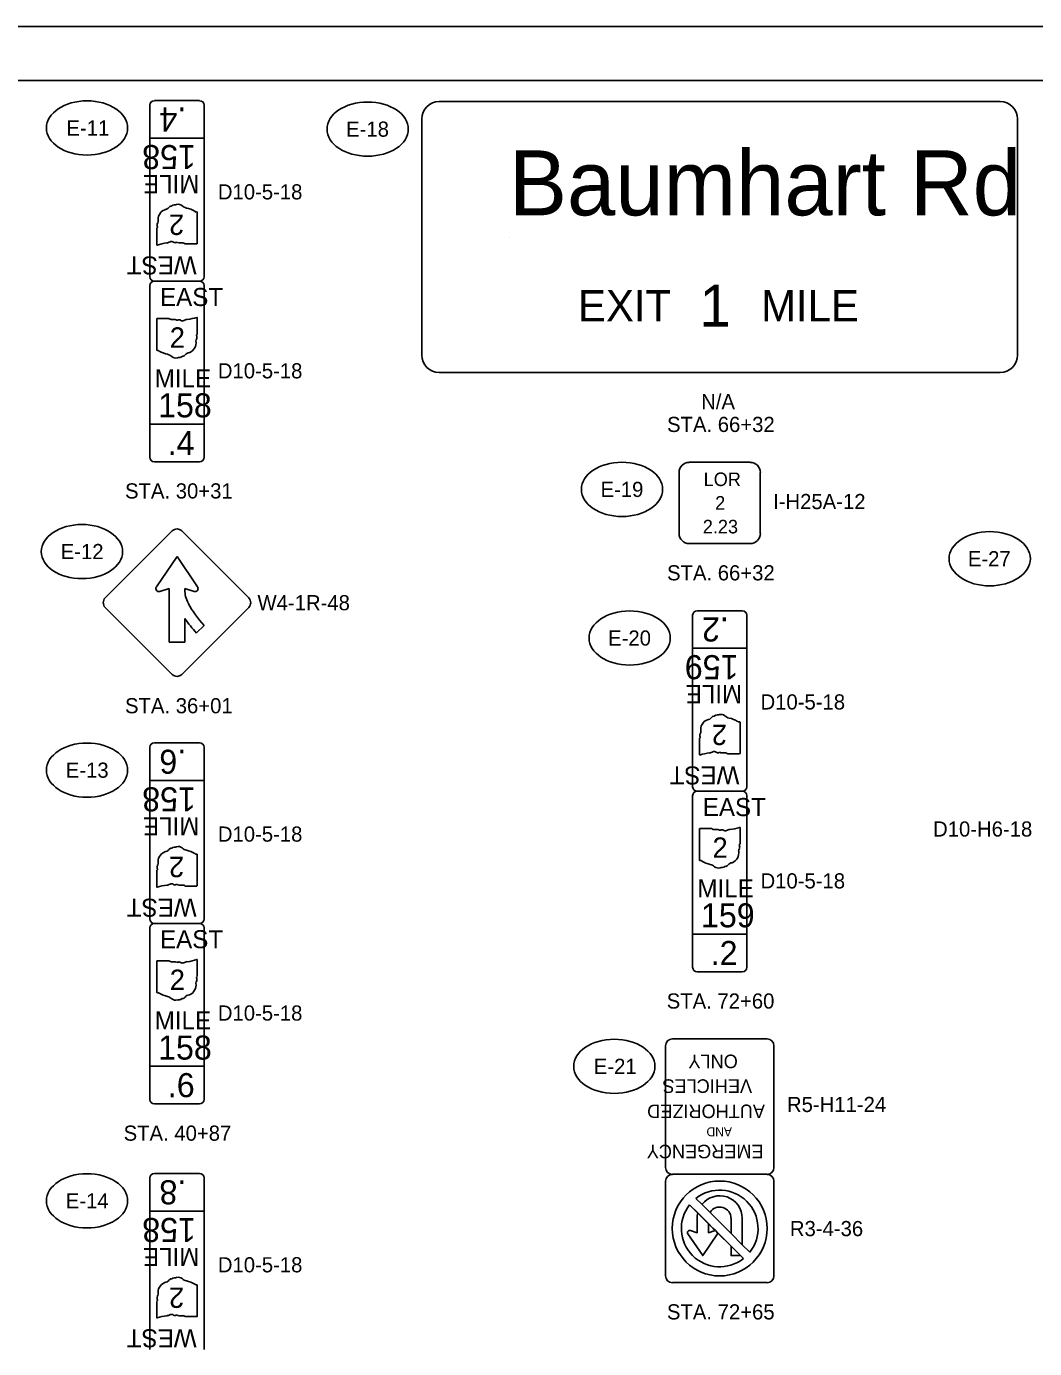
# Model space of a CAD drawing. Extents: x 0 to 34, y 0 to 22.
# Drawn here: x 9.32 to 18.63, y 9.79 to 22 of the extents above; entities that cross this region are included whole.
import ezdxf

# ---------------------------------------------------------------- set-up
doc = ezdxf.new("R2010")
doc.units = 0
for name, color, linetype in [('SH_Border', 7, 'Continuous'), ('SH_Cut_Line', 7, 'Continuous'), ('SH_Text', 7, 'Continuous'), ('SN_P_Signs', 7, 'Continuous')]:
    doc.layers.add(name, color=color, linetype=linetype)

msp = doc.modelspace()

# ---------------------------------------------------------------- linework, layer by layer
at = {"layer": 'SH_Border'}
msp.add_lwpolyline([(1.5, 21.5), (33.5, 21.5), (33.5, 0.5), (1.5, 0.5)], close=True, dxfattribs=at)
at = {"layer": 'SH_Cut_Line'}
msp.add_lwpolyline([(0, 0), (34, 0), (34, 22), (0, 22)], close=True, dxfattribs=at)
at = {"layer": 'SH_Text'}
for points in [[(13.134, 21.306), (18.314, 21.306)], [(12.974, 18.966), (12.974, 21.146)], [(18.474, 21.146), (18.474, 18.966)], [(18.314, 18.806), (13.134, 18.806)]]:
    msp.add_lwpolyline(points, dxfattribs=at)
for centre, start, end in [((13.134, 21.146), 90, 180), ((18.314, 21.146), 0, 90), ((13.134, 18.966), 180, 270), ((18.314, 18.966), 270, 0)]:
    msp.add_arc(centre, 0.16, start, end, dxfattribs=at)
for centre in [(9.883, 21.063), (12.474, 21.052), (14.822, 17.726), (9.836, 17.152), (18.217, 17.086), (14.893, 16.354), (9.883, 15.134), (14.751, 12.4), (9.883, 11.158)]:
    msp.add_ellipse(centre, major_axis=(0.375, 0), ratio=0.666667, dxfattribs=at)
at = {"layer": 'SN_P_Signs'}
for p, q in [((10.464, 20.968), (10.964, 20.968)), ((10.901, 19.998), (10.901, 20.283)), ((10.714, 20.169), (10.714, 20.169)), ((10.526, 20.135), (10.526, 19.986)), ((10.526, 20.135), (10.526, 20.135)), ((13.786, 20.056), (13.786, 20.056)), ((10.788, 19.993), (10.898, 19.993)), ((10.526, 19.298), (10.526, 19.014)), ((10.64, 19.303), (10.53, 19.303)), ((10.901, 19.161), (10.901, 19.31)), ((10.714, 19.127), (10.714, 19.127)), ((10.901, 19.161), (10.901, 19.161)), ((10.964, 18.329), (10.464, 18.329)), ((10.523, 16.827), (10.714, 17.107)), ((10.714, 17.107), (10.904, 16.827)), ((10.641, 16.811), (10.556, 16.783)), ((10.641, 16.316), (10.641, 16.811)), ((10.872, 16.783), (10.787, 16.811)), ((10.787, 16.811), (10.787, 16.801)), ((10.787, 16.535), (10.787, 16.316)), ((10.964, 16.471), (10.894, 16.401)), ((10.787, 16.316), (10.641, 16.316)), ((15.474, 16.259), (15.974, 16.259)), ((15.912, 15.289), (15.912, 15.574)), ((15.537, 15.426), (15.537, 15.278)), ((15.537, 15.426), (15.537, 15.426)), ((15.724, 15.46), (15.724, 15.46)), ((15.798, 15.285), (15.908, 15.285)), ((10.464, 15.039), (10.964, 15.039)), ((15.537, 14.589), (15.537, 14.305)), ((15.65, 14.594), (15.541, 14.594)), ((15.912, 14.452), (15.912, 14.601)), ((15.724, 14.419), (15.724, 14.419)), ((15.912, 14.453), (15.912, 14.452)), ((10.901, 14.069), (10.901, 14.354)), ((10.526, 14.206), (10.526, 14.057)), ((10.526, 14.206), (10.526, 14.206)), ((10.714, 14.24), (10.714, 14.24)), ((10.788, 14.064), (10.898, 14.064)), ((15.974, 13.62), (15.474, 13.62)), ((10.526, 13.369), (10.526, 13.085)), ((10.64, 13.374), (10.53, 13.374)), ((10.901, 13.232), (10.901, 13.381)), ((10.714, 13.198), (10.714, 13.198)), ((10.901, 13.232), (10.901, 13.232)), ((10.964, 12.4), (10.464, 12.4)), ((15.446, 11.122), (15.944, 10.625)), ((10.464, 11.063), (10.964, 11.063)), ((15.516, 10.864), (15.516, 10.997)), ((15.829, 10.858), (15.829, 10.997)), ((15.933, 10.753), (15.933, 10.997)), ((15.516, 10.864), (15.455, 10.884)), ((15.62, 10.864), (15.62, 10.948)), ((15.682, 10.884), (15.62, 10.864)), ((15.431, 10.852), (15.568, 10.653)), ((15.568, 10.653), (15.705, 10.852)), ((15.829, 10.653), (15.829, 10.74)), ((15.829, 10.653), (15.915, 10.653)), ((10.901, 10.094), (10.901, 10.378)), ((10.714, 10.264), (10.714, 10.264)), ((10.526, 10.23), (10.526, 10.082)), ((10.526, 10.23), (10.526, 10.23)), ((10.788, 10.089), (10.898, 10.089))]:
    msp.add_line(p, q, dxfattribs=at)
for points in [[(10.464, 19.69), (10.464, 21.273)], [(10.505, 21.315), (10.922, 21.315)], [(10.964, 21.273), (10.964, 19.69)], [(10.464, 18.023), (10.464, 19.607)], [(10.922, 19.648), (10.505, 19.648)], [(10.505, 19.648), (10.922, 19.648)], [(10.964, 19.607), (10.964, 18.023)], [(10.922, 17.982), (10.505, 17.982)], [(16.006, 17.976), (15.443, 17.976)], [(15.349, 17.882), (15.349, 17.32)], [(16.099, 17.32), (16.099, 17.882)], [(10.67, 17.343), (10.051, 16.725)], [(11.377, 16.725), (10.758, 17.343)], [(15.443, 17.226), (16.006, 17.226)], [(10.051, 16.636), (10.67, 16.017)], [(10.758, 16.017), (11.377, 16.636)], [(15.516, 16.606), (15.933, 16.606)], [(15.474, 14.981), (15.474, 16.564)], [(15.974, 16.564), (15.974, 14.981)], [(10.505, 15.386), (10.922, 15.386)], [(10.464, 13.761), (10.464, 15.344)], [(10.964, 15.344), (10.964, 13.761)], [(15.474, 13.314), (15.474, 14.898)], [(15.933, 14.939), (15.516, 14.939)], [(15.516, 14.939), (15.933, 14.939)], [(15.974, 14.898), (15.974, 13.314)], [(10.464, 12.094), (10.464, 13.678)], [(10.922, 13.719), (10.505, 13.719)], [(10.505, 13.719), (10.922, 13.719)], [(10.964, 13.678), (10.964, 12.094)], [(15.933, 13.273), (15.516, 13.273)], [(15.224, 12.59), (15.224, 11.465)], [(16.162, 12.653), (15.287, 12.653)], [(16.224, 11.465), (16.224, 12.59)], [(10.922, 12.053), (10.505, 12.053)], [(10.464, 9.785), (10.464, 11.369)], [(10.505, 11.41), (10.922, 11.41)], [(10.964, 11.369), (10.964, 9.785)], [(15.287, 11.403), (16.162, 11.403)], [(16.162, 11.403), (15.287, 11.403)], [(15.224, 11.34), (15.224, 10.465)], [(16.224, 10.465), (16.224, 11.34)], [(15.446, 11.122), (15.522, 11.046), (15.62, 10.948), (15.662, 10.906), (15.684, 10.884), (15.708, 10.86), (15.829, 10.74), (15.915, 10.653)], [(15.561, 11.125), (15.505, 11.181)], [(16.003, 10.684), (15.933, 10.753), (15.829, 10.858), (15.721, 10.965), (15.635, 11.051), (15.561, 11.125)], [(15.561, 11.125), (15.635, 11.051)], [(15.516, 10.997), (15.516, 10.864), (15.455, 10.884)], [(15.682, 10.884), (15.62, 10.864), (15.62, 10.948), (15.522, 11.046)], [(15.829, 10.858), (15.933, 10.753), (15.933, 10.997)], [(15.829, 10.997), (15.829, 10.858)], [(15.708, 10.86), (15.684, 10.884)], [(15.431, 10.852), (15.568, 10.653), (15.705, 10.852)], [(15.915, 10.653), (15.829, 10.74), (15.829, 10.653), (15.915, 10.653)], [(15.915, 10.653), (15.944, 10.625)], [(15.287, 10.403), (16.162, 10.403)]]:
    msp.add_lwpolyline(points, dxfattribs=at)
msp.add_circle((15.724, 10.903), 0.438, dxfattribs=at)
for centre, radius, start, end in [((10.505, 21.273), 0.0417, 90, 180), ((10.922, 21.273), 0.0417, 0, 90), ((10.638, 20.216), 0.0995, 112.3089, 188.9858), ((10.596, 20.363), 0.0545, 274.4031, 322.5768), ((10.665, 20.31), 0.0321, 102.8732, 143.2771), ((10.661, 20.35), 0.00855, 245.7517, 312.6484), ((10.688, 20.322), 0.0304, 88.777, 135.5493), ((10.693, 20.399), 0.0468, 265.6951, 291.2099), ((10.726, 20.301), 0.057, 50.7004, 106.2918), ((10.823, 20.411), 0.0899, 227.1842, 255.836), ((10.737, 20.044), 0.287, 60.4129, 77.1985), ((10.889, 20.299), 0.0121, 209.7484, 273.2717), ((10.896, 20.254), 0.0334, 87.339, 100.6039), ((10.897, 20.283), 0.00438, 351.9584, 78.3066), ((10.531, 20.136), 0.00447, 109.6038, 187.7341), ((10.527, 20.146), 0.00646, 287.944, 30.337), ((10.568, 20.165), 0.0388, 160.033, 203.6496), ((10.511, 20.197), 0.0282, 316.8065, 6.9296), ((10.53, 19.986), 0.00417, 171.8621, 277.738), ((10.66, 19.605), 0.398, 95.8445, 108.9065), ((10.609, 20.08), 0.08, 277.3462, 300.7689), ((10.663, 19.984), 0.0304, 53.8562, 114.8282), ((10.695, 20.029), 0.0253, 234.4667, 299.1411), ((10.713, 19.996), 0.0122, 39.7921, 117.1024), ((10.748, 20.153), 0.151, 260.4867, 274.9883), ((10.762, 19.96), 0.0421, 51.6195, 91.1119), ((10.897, 19.998), 0.00434, 278.1301, 8.1301), ((10.505, 19.69), 0.0417, 180, 270), ((10.922, 19.69), 0.0417, 270, 360), ((10.505, 19.607), 0.0417, 90, 180), ((10.922, 19.607), 0.0417, 0, 90), ((10.531, 19.299), 0.00434, 98.1301, 188.1301), ((10.666, 19.336), 0.0421, 231.6195, 271.1119), ((10.68, 19.143), 0.151, 80.4867, 94.9883), ((10.714, 19.3), 0.0122, 219.7921, 297.1024), ((10.732, 19.267), 0.0253, 54.4667, 119.1411), ((10.765, 19.312), 0.0304, 233.8562, 294.8282), ((10.818, 19.216), 0.08, 97.3462, 120.7689), ((10.768, 19.691), 0.398, 275.8445, 288.9065), ((10.897, 19.311), 0.00417, 351.8621, 97.738), ((10.79, 19.08), 0.0995, 292.3089, 8.9858), ((10.916, 19.099), 0.0282, 136.8065, 186.9296), ((10.9, 19.15), 0.00646, 107.944, 210.337), ((10.859, 19.131), 0.0388, 340.033, 23.6496), ((10.897, 19.161), 0.00447, 289.6038, 7.7341), ((10.531, 19.013), 0.00438, 171.9584, 258.3066), ((10.531, 19.042), 0.0334, 267.339, 280.6039), ((10.538, 18.997), 0.0121, 29.7484, 93.2717), ((10.69, 19.253), 0.287, 240.4129, 257.1985), ((10.605, 18.886), 0.0899, 47.1842, 75.836), ((10.702, 18.996), 0.057, 230.7004, 286.2918), ((10.735, 18.897), 0.0468, 85.6951, 111.2099), ((10.739, 18.974), 0.0304, 268.777, 315.5493), ((10.767, 18.947), 0.00855, 65.7517, 132.6484), ((10.763, 18.986), 0.0321, 282.8732, 323.2771), ((10.832, 18.934), 0.0545, 94.4031, 142.5768), ((10.505, 18.023), 0.0417, 180, 270), ((10.922, 18.023), 0.0417, 270, 0), ((15.443, 17.882), 0.0938, 90, 180), ((16.006, 17.882), 0.0938, 0, 90), ((10.714, 17.299), 0.0625, 45, 135), ((15.443, 17.32), 0.0938, 180, 270), ((16.006, 17.32), 0.0938, 270, 0), ((10.095, 16.68), 0.0625, 135, 225), ((10.547, 16.811), 0.0287, 145.86, 287.8182), ((11.052, 16.801), 0.266, 180, 207.6427), ((10.88, 16.811), 0.0287, 252.1818, 34.14), ((11.332, 16.68), 0.0625, 315, 45), ((11.638, 17.107), 0.927, 207.6427, 223.3789), ((15.516, 16.564), 0.0417, 90, 180), ((15.933, 16.564), 0.0417, 0, 90), ((11.638, 17.107), 1.026, 213.9044, 223.5353), ((10.714, 16.062), 0.0625, 225, 315), ((15.675, 15.602), 0.0321, 102.8732, 143.2771), ((15.672, 15.641), 0.00855, 245.7517, 312.6484), ((15.699, 15.613), 0.0304, 88.777, 135.5493), ((15.703, 15.69), 0.0468, 265.6951, 291.2099), ((15.736, 15.592), 0.057, 50.7004, 106.2918), ((15.833, 15.702), 0.0899, 227.1842, 255.836), ((15.648, 15.508), 0.0995, 112.3089, 188.9858), ((15.606, 15.654), 0.0545, 274.4031, 322.5768), ((15.748, 15.335), 0.287, 60.4129, 77.1985), ((15.9, 15.591), 0.0121, 209.7484, 273.2717), ((15.907, 15.546), 0.0334, 87.339, 100.6039), ((15.908, 15.575), 0.00438, 351.9584, 78.3066), ((10.505, 15.344), 0.0417, 90, 180), ((10.922, 15.344), 0.0417, 0, 90), ((15.541, 15.427), 0.00447, 109.6038, 187.7341), ((15.579, 15.456), 0.0388, 160.033, 203.6496), ((15.538, 15.437), 0.00646, 287.944, 30.337), ((15.522, 15.489), 0.0282, 316.8065, 6.9296), ((15.541, 15.277), 0.00417, 171.8621, 277.738), ((15.67, 14.897), 0.398, 95.8445, 108.9065), ((15.62, 15.372), 0.08, 277.3462, 300.7689), ((15.673, 15.275), 0.0304, 53.8562, 114.8282), ((15.706, 15.32), 0.0253, 234.4667, 299.1411), ((15.724, 15.287), 0.0122, 39.7921, 117.1024), ((15.758, 15.444), 0.151, 260.4867, 274.9883), ((15.772, 15.252), 0.0421, 51.6195, 91.1119), ((15.908, 15.289), 0.00434, 278.1301, 8.1301), ((15.516, 14.981), 0.0417, 180, 270), ((15.516, 14.898), 0.0417, 90, 180), ((15.933, 14.981), 0.0417, 270, 360), ((15.933, 14.898), 0.0417, 0, 90), ((15.541, 14.59), 0.00434, 98.1301, 188.1301), ((15.677, 14.627), 0.0421, 231.6195, 271.1119), ((15.691, 14.435), 0.151, 80.4867, 94.9883), ((15.725, 14.592), 0.0122, 219.7921, 297.1024), ((15.743, 14.559), 0.0253, 54.4667, 119.1411), ((15.775, 14.604), 0.0304, 233.8562, 294.8282), ((15.829, 14.507), 0.08, 97.3462, 120.7689), ((15.778, 14.982), 0.398, 275.8445, 288.9065), ((15.908, 14.602), 0.00417, 351.8621, 97.738), ((10.665, 14.382), 0.0321, 102.8732, 143.2771), ((10.661, 14.421), 0.00855, 245.7517, 312.6484), ((10.688, 14.393), 0.0304, 88.777, 135.5493), ((10.693, 14.47), 0.0468, 265.6951, 291.2099), ((10.726, 14.372), 0.057, 50.7004, 106.2918), ((10.823, 14.482), 0.0899, 227.1842, 255.836), ((15.927, 14.39), 0.0282, 136.8065, 186.9296), ((15.911, 14.442), 0.00646, 107.944, 210.337), ((15.87, 14.423), 0.0388, 340.033, 23.6496), ((15.907, 14.452), 0.00447, 289.6038, 7.7341), ((10.638, 14.288), 0.0995, 112.3089, 188.9858), ((10.596, 14.434), 0.0545, 274.4031, 322.5768), ((10.737, 14.115), 0.287, 60.4129, 77.1985), ((10.889, 14.37), 0.0121, 209.7484, 273.2717), ((10.896, 14.325), 0.0334, 87.339, 100.6039), ((10.897, 14.355), 0.00438, 351.9584, 78.3066), ((15.541, 14.304), 0.00438, 171.9584, 258.3066), ((15.542, 14.333), 0.0334, 267.339, 280.6039), ((15.549, 14.288), 0.0121, 29.7484, 93.2717), ((15.701, 14.544), 0.287, 240.4129, 257.1985), ((15.801, 14.371), 0.0995, 292.3089, 8.9858), ((10.531, 14.207), 0.00447, 109.6038, 187.7341), ((10.527, 14.217), 0.00646, 287.944, 30.337), ((10.568, 14.236), 0.0388, 160.033, 203.6496), ((10.511, 14.269), 0.0282, 316.8065, 6.9296), ((15.615, 14.177), 0.0899, 47.1842, 75.836), ((15.713, 14.287), 0.057, 230.7004, 286.2918), ((15.746, 14.189), 0.0468, 85.6951, 111.2099), ((15.75, 14.266), 0.0304, 268.777, 315.5493), ((15.777, 14.238), 0.00855, 65.7517, 132.6484), ((15.774, 14.277), 0.0321, 282.8732, 323.2771), ((15.843, 14.225), 0.0545, 94.4031, 142.5768), ((10.53, 14.057), 0.00417, 171.8621, 277.738), ((10.66, 13.676), 0.398, 95.8445, 108.9065), ((10.609, 14.151), 0.08, 277.3462, 300.7689), ((10.663, 14.055), 0.0304, 53.8562, 114.8282), ((10.695, 14.1), 0.0253, 234.4667, 299.1411), ((10.713, 14.067), 0.0122, 39.7921, 117.1024), ((10.748, 14.224), 0.151, 260.4867, 274.9883), ((10.762, 14.031), 0.0421, 51.6195, 91.1119), ((10.897, 14.069), 0.00434, 278.1301, 8.1301), ((10.505, 13.761), 0.0417, 180, 270), ((10.505, 13.678), 0.0417, 90, 180), ((10.922, 13.761), 0.0417, 270, 360), ((10.922, 13.678), 0.0417, 0, 90), ((10.531, 13.37), 0.00434, 98.1301, 188.1301), ((10.666, 13.407), 0.0421, 231.6195, 271.1119), ((10.68, 13.214), 0.151, 80.4867, 94.9883), ((10.714, 13.371), 0.0122, 219.7921, 297.1024), ((10.732, 13.338), 0.0253, 54.4667, 119.1411), ((10.765, 13.384), 0.0304, 233.8562, 294.8282), ((10.818, 13.287), 0.08, 97.3462, 120.7689), ((10.768, 13.762), 0.398, 275.8445, 288.9065), ((10.897, 13.382), 0.00417, 351.8621, 97.738), ((15.516, 13.314), 0.0417, 180, 270), ((15.933, 13.314), 0.0417, 270, 0), ((10.916, 13.17), 0.0282, 136.8065, 186.9296), ((10.9, 13.221), 0.00646, 107.944, 210.337), ((10.859, 13.203), 0.0388, 340.033, 23.6496), ((10.897, 13.232), 0.00447, 289.6038, 7.7341), ((10.531, 13.084), 0.00438, 171.9584, 258.3066), ((10.531, 13.113), 0.0334, 267.339, 280.6039), ((10.538, 13.068), 0.0121, 29.7484, 93.2717), ((10.69, 13.324), 0.287, 240.4129, 257.1985), ((10.79, 13.151), 0.0995, 292.3089, 8.9858), ((10.605, 12.957), 0.0899, 47.1842, 75.836), ((10.702, 13.067), 0.057, 230.7004, 286.2918), ((10.735, 12.968), 0.0468, 85.6951, 111.2099), ((10.739, 13.046), 0.0304, 268.777, 315.5493), ((10.767, 13.018), 0.00855, 65.7517, 132.6484), ((10.763, 13.057), 0.0321, 282.8732, 323.2771), ((10.832, 13.005), 0.0545, 94.4031, 142.5768), ((15.287, 12.59), 0.0625, 90, 180), ((16.162, 12.59), 0.0625, 0, 90), ((10.505, 12.094), 0.0417, 180, 270), ((10.922, 12.094), 0.0417, 270, 0), ((10.505, 11.369), 0.0417, 90, 180), ((10.922, 11.369), 0.0417, 0, 90), ((15.287, 11.465), 0.0625, 180, 270), ((15.287, 11.34), 0.0625, 90, 180), ((16.162, 11.465), 0.0625, 270, 360), ((16.162, 11.34), 0.0625, 0, 90), ((15.724, 10.903), 0.438, 0, 180), ((15.724, 10.903), 0.354, 321.7563, 128.2437), ((15.724, 10.903), 0.354, 321.7563, 128.2437), ((15.724, 10.903), 0.354, 141.7563, 308.2437), ((15.724, 10.903), 0.354, 141.7563, 308.2437), ((15.724, 10.997), 0.208, 0, 141.7881), ((15.724, 10.997), 0.208, 0, 141.7881), ((15.724, 10.997), 0.208, 166.2115, 180), ((15.724, 10.997), 0.208, 166.2115, 180), ((15.724, 10.997), 0.104, 0, 148.6739), ((15.724, 10.997), 0.104, 0, 148.6739), ((15.724, 10.903), 0.438, 180, 0), ((15.448, 10.864), 0.0208, 72.6382, 214.5163), ((15.448, 10.864), 0.0208, 72.6382, 214.5163), ((15.688, 10.864), 0.0208, 100.7673, 107.3618), ((15.688, 10.864), 0.0208, 100.7673, 107.3618), ((15.688, 10.864), 0.0208, 325.4837, 349.2327), ((15.688, 10.864), 0.0208, 325.4837, 349.2327), ((10.638, 10.312), 0.0995, 112.3089, 188.9858), ((10.596, 10.458), 0.0545, 274.4031, 322.5768), ((10.665, 10.406), 0.0321, 102.8732, 143.2771), ((10.661, 10.445), 0.00855, 245.7517, 312.6484), ((10.688, 10.417), 0.0304, 88.777, 135.5493), ((10.693, 10.494), 0.0468, 265.6951, 291.2099), ((10.726, 10.396), 0.057, 50.7004, 106.2918), ((10.823, 10.506), 0.0899, 227.1842, 255.836), ((10.737, 10.139), 0.287, 60.4129, 77.1985), ((10.889, 10.395), 0.0121, 209.7484, 273.2717), ((10.896, 10.35), 0.0334, 87.339, 100.6039), ((10.897, 10.379), 0.00438, 351.9584, 78.3066), ((15.287, 10.465), 0.0625, 180, 270), ((16.162, 10.465), 0.0625, 270, 0), ((10.568, 10.26), 0.0388, 160.033, 203.6496), ((10.511, 10.293), 0.0282, 316.8065, 6.9296), ((10.531, 10.231), 0.00447, 109.6038, 187.7341), ((10.527, 10.241), 0.00646, 287.944, 30.337), ((10.53, 10.081), 0.00417, 171.8621, 277.738), ((10.66, 9.701), 0.398, 95.8445, 108.9065), ((10.609, 10.176), 0.08, 277.3462, 300.7689), ((10.663, 10.079), 0.0304, 53.8562, 114.8282), ((10.695, 10.124), 0.0253, 234.4667, 299.1411), ((10.713, 10.091), 0.0122, 39.7921, 117.1024), ((10.748, 10.248), 0.151, 260.4867, 274.9883), ((10.762, 10.056), 0.0421, 51.6195, 91.1119), ((10.897, 10.093), 0.00434, 278.1301, 8.1301)]:
    msp.add_arc(centre, radius, start, end, dxfattribs=at)

# ---------------------------------------------------------------- texts
at = {"layer": 'SH_Text'}
for s, p in [('E-11', (9.693, 20.993)), ('E-18', (12.275, 20.982)), ('D10-5-18', (11.091, 20.403)), ('D10-5-18', (11.091, 18.751)), ('N/A', (15.553, 18.466)), ('STA. 66+32', (15.238, 18.256)), ('STA. 30+31', (10.234, 17.642)), ('E-19', (14.624, 17.656)), ('I-H25A-12', (16.217, 17.544)), ('E-12', (9.64, 17.082)), ('E-27', (18.015, 17.016)), ('STA. 66+32', (15.238, 16.886)), ('W4-1R-48', (11.457, 16.61)), ('E-20', (14.694, 16.284)), ('STA. 36+01', (10.234, 15.659)), ('D10-5-18', (16.101, 15.694)), ('E-13', (9.687, 15.064)), ('D10-H6-18', (17.694, 14.521)), ('D10-5-18', (11.091, 14.474)), ('D10-5-18', (16.101, 14.042)), ('STA. 72+60', (15.235, 12.933)), ('D10-5-18', (11.091, 12.822)), ('E-21', (14.562, 12.33)), ('R5-H11-24', (16.345, 11.978)), ('STA. 40+87', (10.221, 11.713)), ('E-14', (9.687, 11.088)), ('R3-4-36', (16.372, 10.832)), ('D10-5-18', (11.091, 10.498)), ('STA. 72+65', (15.237, 10.063))]:
    msp.add_text(s, height=0.14, dxfattribs=at).set_placement(p)
at = {"layer": 'SN_P_Signs'}
for s, height, p in [('.4', 0.2222, (10.8, 21.252)), ('158', 0.2222, (10.888, 20.905)), ('MILE', 0.1667, (10.92, 20.627)), ('2', 0.188, (10.78, 20.263)), ('WEST', 0.1667, (10.895, 19.877)), ('.2', 0.2222, (15.808, 16.544)), ('159', 0.2222, (15.898, 16.196)), ('MILE', 0.1667, (15.931, 15.919)), ('2', 0.188, (15.791, 15.554)), ('.6', 0.2222, (10.799, 15.323)), ('WEST', 0.1667, (15.906, 15.169)), ('158', 0.2222, (10.888, 14.976)), ('MILE', 0.1667, (10.92, 14.698)), ('2', 0.188, (10.78, 14.334)), ('WEST', 0.1667, (10.895, 13.948)), ('ONLY', 0.1251, (15.891, 12.508)), ('VEHICLES', 0.1251, (16.023, 12.28)), ('AUTHORIZED', 0.1251, (16.142, 12.047)), ('AND', 0.0833, (15.837, 11.837)), ('EMERGENCY', 0.1251, (16.129, 11.676)), ('.8', 0.2222, (10.799, 11.348)), ('158', 0.2222, (10.888, 11)), ('MILE', 0.1667, (10.92, 10.723)), ('2', 0.188, (10.78, 10.358)), ('WEST', 0.1667, (10.895, 9.973))]:
    msp.add_text(s, height=height, rotation=180, dxfattribs=at).set_placement(p)
for s, height, p in [('Baumhart Rd', 0.60001, (13.779, 20.256)), ('EAST', 0.1667, (10.557, 19.419)), ('EXIT', 0.2892, (14.416, 19.277)), ('1', 0.386, (15.538, 19.229)), ('MILE', 0.2892, (16.106, 19.277)), ('2', 0.188, (10.647, 19.034)), ('MILE', 0.1667, (10.508, 18.669)), ('158', 0.2222, (10.539, 18.391)), ('.4', 0.2222, (10.627, 18.044)), ('LOR', 0.125, (15.576, 17.757)), ('2', 0.125, (15.682, 17.539)), ('2.23', 0.125, (15.568, 17.32)), ('EAST', 0.1667, (15.568, 14.71)), ('2', 0.188, (15.658, 14.325)), ('MILE', 0.1667, (15.518, 13.96)), ('159', 0.2222, (15.551, 13.683)), ('EAST', 0.1667, (10.557, 13.49)), ('.2', 0.2222, (15.641, 13.335)), ('2', 0.188, (10.647, 13.105)), ('MILE', 0.1667, (10.508, 12.74)), ('158', 0.2222, (10.539, 12.462)), ('.6', 0.2222, (10.629, 12.115))]:
    msp.add_text(s, height=height, dxfattribs=at).set_placement(p)

doc.saveas('drawing.dxf')
